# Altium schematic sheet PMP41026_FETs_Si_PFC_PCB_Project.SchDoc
size 431 x 279 mm; Date: Not shown in title block; ApprovedBy: Not shown in title block; CheckedBy: Not shown in title block; Author: Not shown in title block; CompanyName: Not shown in title block; Engineer: Not shown in title block; Organization: Not shown in title block; Address1: Not shown in title block; Address2: Not shown in title block; Address3: Not shown in title block; Address4: Not shown in title block; DocumentNumber: 1; Revision: Use project parameter SCH_Rev; SheetNumber: 1; SheetTotal: 2; PageSetup: Record=PageOptions¦CenterHorizontal=True¦CenterVertical=True¦PrintScale=1.00¦XCorrection=1.00¦YCorrection=1.00¦PrintKind=0¦BorderSize=5000000¦LeftOffset=0¦BottomOffset=0¦Orientation=2¦PaperLength=1000¦PaperWidth=1000¦Scale=100¦PaperSource=15¦PrintQuality=600¦MediaType=1¦DitherType=10¦PaperKind=Letter¦PrintScaleMode=1
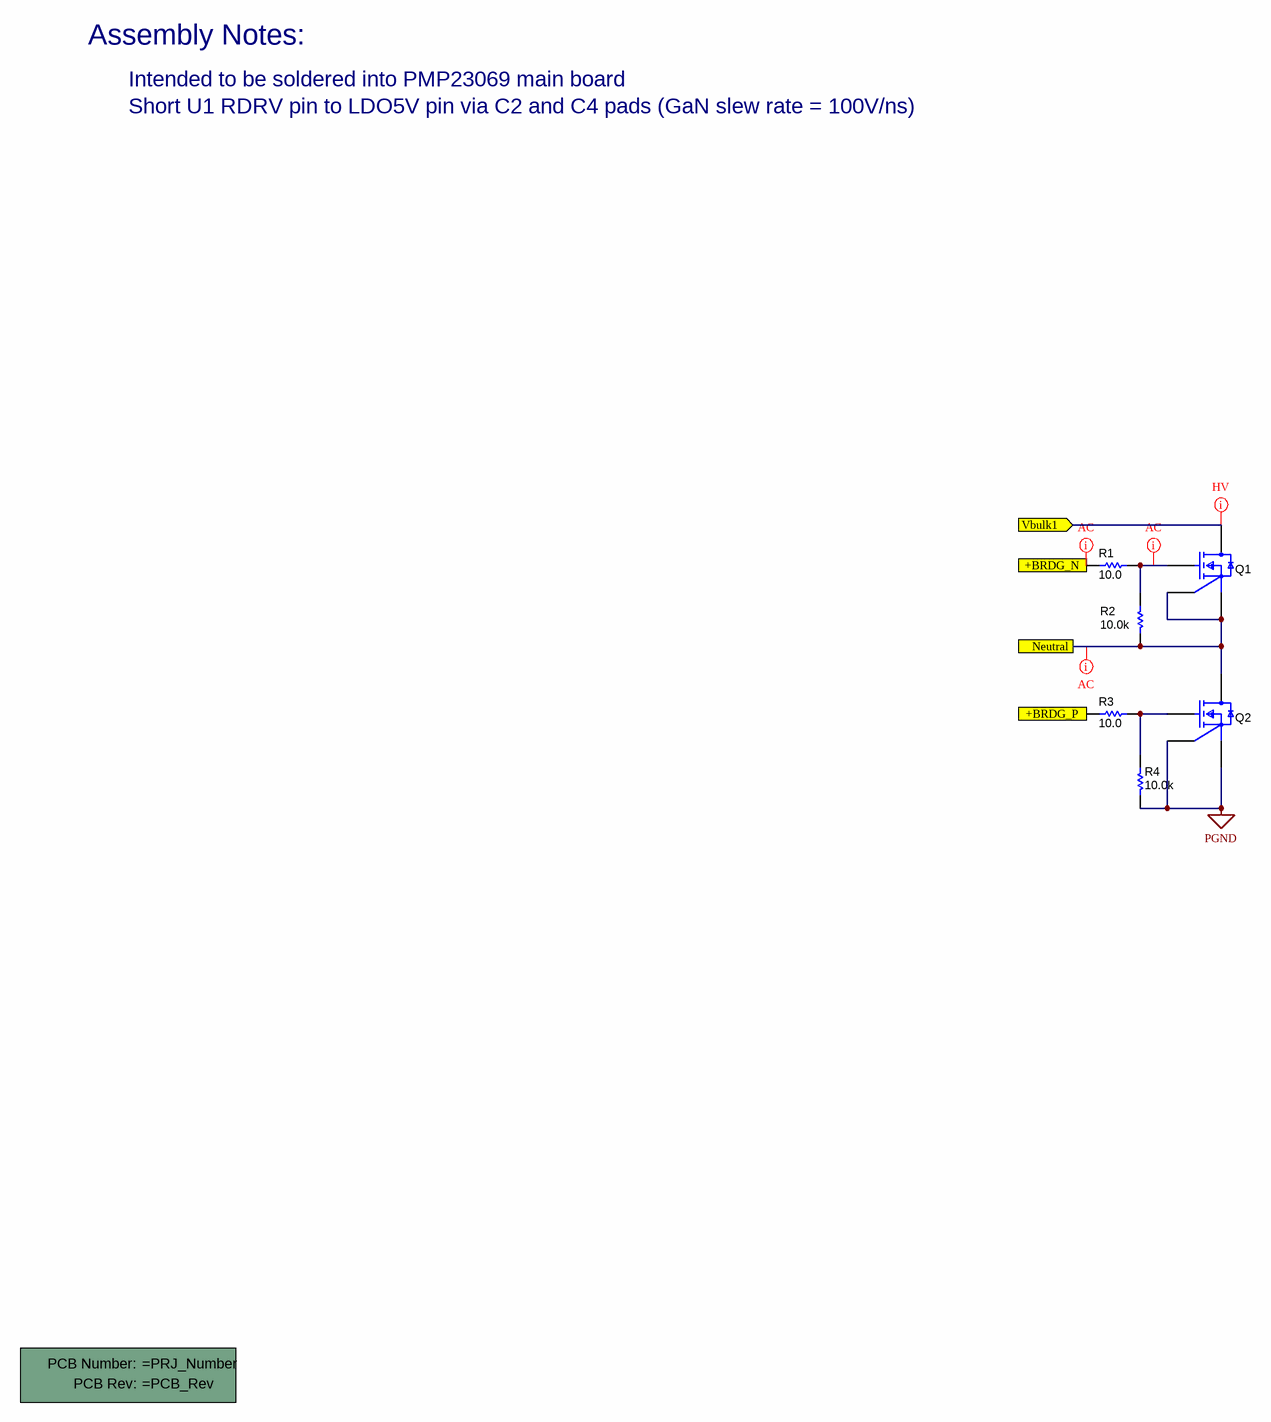
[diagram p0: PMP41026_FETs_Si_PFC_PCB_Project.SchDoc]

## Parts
!PCB2  Printed Circuit Board  (value not drawn)  (mechanical)
Q1  IPT60R022S7XTMA1  [FP-IPT60R080G7XTMA1_HSOF-8-MFG]  (value not drawn)
Q2  IPT60R022S7XTMA1  [FP-IPT60R080G7XTMA1_HSOF-8-MFG]  (value not drawn)
R1  ValueDisplayed: 10.0  [0603]  (hidden comment: CRCW060310R0FKEA)
R2  ValueDisplayed: 10.0k  [0603]  (hidden comment: CRCW060310K0FKEA)
R3  ValueDisplayed: 10.0  [0603]  (hidden comment: CRCW060310R0FKEA)
R4  ValueDisplayed: 10.0k  [0603]  (hidden comment: CRCW060310K0FKEA)

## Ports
+BRDG_N (in), +BRDG_P (in), Neutral, Vbulk1 (in)

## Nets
PGND: Q2.2(Driver_Source) Q2.3-4-5-6-7-8(Source) R4.1
+BRDG_N: R1.1 ; port +BRDG_N
+BRDG_P: R3.1 ; port +BRDG_P
Neutral: Q1.2(Driver_Source) Q1.3-4-5-6-7-8(Source) Q2.9(Drain) R2.1 ; port Neutral
Vbulk1: Q1.9(Drain) ; port Vbulk1
NetQ1_1: Q1.1(Gate) R1.2 R2.2
NetQ2_1: Q2.1(Gate) R3.2 R4.2

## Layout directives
net class HV: Vbulk1
net class AC: +BRDG_N, NetQ1_1, Neutral

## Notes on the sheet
- Assembly Notes:
- Intended to be soldered into PMP23069 main board
- Short U1 RDRV pin to LDO5V pin via C2 and C4 pads (GaN slew rate = 100V/ns)

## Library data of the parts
!PCB2 = CMP-0003618-2: Manufacturer: Any
Q1 Q2 = CMP-0086487-1: N-Channel 600V 23A (Tc) 390W (Tc) Surface Mount PG-HSOF-8-2; Manufacturer: Infineon; VdsMax_V: 650V; IdsMax_A: 29A; Vgs_V: 20V; AEC Qualified: No; ChMode: False; SizeZ_mm: 2.4mm
R1 R3 = CMP-0022003-4: RES, 10.0, 1%, 0.1 W, AEC-Q200 Grade 0, 0603; Manufacturer: Vishay-Dale; Value: 10.0; Res_ohm: 10; Value_Code: 10R0; Power_W: 100mW; Value2: 0.1W; VDC_V: 75V; TempCo: 100 ppm/C; SizeArea_mm2: 1.28; SizeX_mm: 1.6; SizeY_mm: 0.8; SizeZ_mm: 1; EIA_Code: E96; AEC Category: Q200; AEC Qualified: Y; AEC Grade: 0
R2 R4 = CMP-0021998-4: RES, 10.0 k, 1%, 0.1 W, AEC-Q200 Grade 0, 0603; Manufacturer: Vishay-Dale; Value: 10.0k; Res_ohm: 10k; Value_Code: 10k0; Power_W: 100mW; Value2: 0.1W; VDC_V: 75V; TempCo: 100 ppm/C; SizeArea_mm2: 1.28; SizeX_mm: 1.6; SizeY_mm: 0.8; SizeZ_mm: 1; EIA_Code: E96; AEC Category: Q200; AEC Qualified: Y; AEC Grade: 0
